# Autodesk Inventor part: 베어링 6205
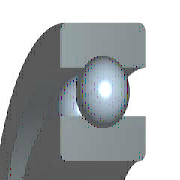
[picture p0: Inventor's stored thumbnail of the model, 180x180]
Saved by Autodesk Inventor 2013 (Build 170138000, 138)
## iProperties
Created: 2015-10
Part Number: 베어링 6205
Material: 강, 연강
Description: 깊은 그루브 볼 베어링
Document SubType Name: Modeling
Standard: KS B 2023
Designer: mdu
Standards Organization: KS
Language: ko-KR
Size Designation: 6205 - 25 x 52 x 15
Categories: <MemberInstance><Categories><Category DisplayName="샤프트 부품" InternalName="7f7aeb1f-a693-4053-b835-cee3144e0d98" Mnemonic="SHFT"><Category DisplayName="베어링" Inter
Density: 1 g/cm^3
IsCustomPart: 1
Author: mdu
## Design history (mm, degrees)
sketch "스케치" dims "d0" = 7.02 (= -0.26 x WD + 0.26 x BD)
  geometry: L1 (3.99, 19.25)-(11.01, 19.25); L2 (7.5, 19.25)-(7.5, 15.74); L3 (7.5, 19.25)-(7.5, 22.76); L4 (4.892, 16.901)-(0, 16.901); L5 (0, 12.5)-(15, 12.5); L6 (4.892, 21.599)-(0, 21.599); L7 (0, 26)-(15, 26); L8 (15, 12.5)-(15, 16.901); L9 (10.108, 16.901)-(15, 16.901); L10 (10.108, 21.599)-(15, 21.599); L11 (15, 26)-(15, 21.599); L12 (-1.4, 0)-(8.4, 0) reference; L13 (0, -0.3)-(0, 5.3) reference
  constraints: 22 end point, 4 point on line, 2 collinear, 2 perpendicular, 2 symmetric about line, 1 midpoint, 1 parallel, 14 other
  dimensions: "d9" = 25 diameter of L5 L12 (= WD); "d11" = 52 diameter of L7 L12 (= BD); "d12" = 15 distance between parallel lines of L8 L13 (= KB); "d13" = 33.802 diameter of L9 L12 (= 0.326 x BD + 0.674 x WD)
revolve "본체" stored, may be unused: angle "d6" = 90 deg
revolve "볼" stored, may be unused: angle "d7" = 90 deg
pattern_circular "IDS_ARRAYBALL[SIMPL:T]" dims angle "d3" = 360 deg
body "Solid1"
fillet "모깎기1" dims "d1" = 1 (= KRS)
other parameters: "WD" = 25 [user parameter; used in 5 equation terms], "BD" = 52 [user parameter; used in 5 equation terms], "KB" = 15 [user parameter; used in 1 equation term], "KRS" = 1 [user parameter; used in 1 equation term], "d4" = 0, "d5" = 0, "d8" = 0, "d14" = 0, "d15" = 0, "BBA" = 0 [user parameter], "BC0" = 7800000 [user parameter], "BC" = 1.4e+07 [user parameter], "BR" = 26 (= 0.5 x BD) [user parameter], "WR" = 12.5 (= 0.5 x WD) [user parameter]
